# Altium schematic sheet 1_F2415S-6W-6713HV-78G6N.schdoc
size 289 x 200 mm; Name: default297x210; Symbol: default297x210; Device: default297x210; Date: 2025.06.26; Rev: V1.1; Size: "A4"; Id: /; File: F2415S-6W-6713HV-78G6N; Sheet: /; @Page No: 1; @Page Count: 1; @Schematic Name: F2415S-6W-6713HV-78G6N; @Project Name: 全桥隔离电源-B2415D-6W-6713HV-78G6N; @Board Name: B2415D-6W-6713HV-78G6N; @Update Date: 2025-06-26; @Create Time: 15:58:33; @Update Time: 15:58:34; @Page Name: F2415S-6W-6713HV-78G6N; @Create Date: 2025-06-26
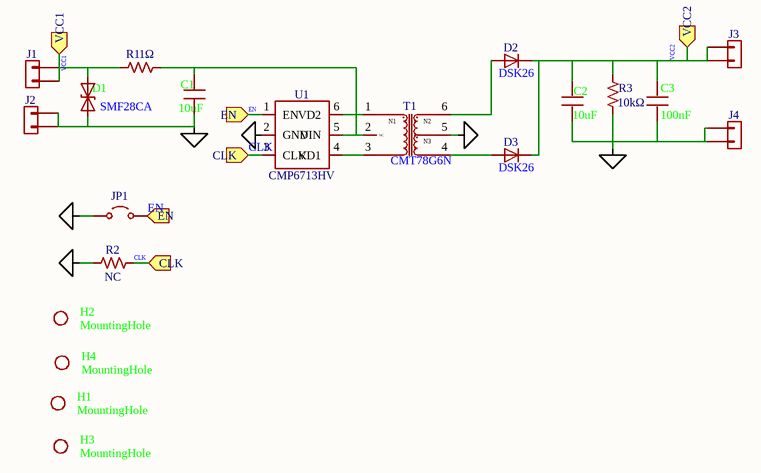
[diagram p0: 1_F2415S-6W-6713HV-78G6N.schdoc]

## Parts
C1  10uF  [C0805]
C2  10uF  [C0805]
C3  100nF  [C0603]
D1  SMF28CA  [SOD-123FL_L2.8-W1.8-LS3.7-BI]
D2  DSK26  [SOD-123_L2.8-W1.8-LS3.7-RD]
D3  DSK26  [SOD-123_L2.8-W1.8-LS3.7-RD]
H1  value MountingHole  [MountingHole:MountingHole_3.2mm_M3]  (hidden comment: Mechanical_MountingHole)
H2  value MountingHole  [MountingHole:MountingHole_3.2mm_M3]  (hidden comment: Mechanical_MountingHole)
H3  value MountingHole  [MountingHole:MountingHole_3.2mm_M3]  (hidden comment: Mechanical_MountingHole)
H4  value MountingHole  [MountingHole:MountingHole_3.2mm_M3]  (hidden comment: Mechanical_MountingHole)
J1  Connector_Generic_Conn_01x02  [Connector_PinHeader_2.54mm:PinHeader_1x02_P2.54mm_Vertical]  (value not drawn)
J2  Connector_Generic_Conn_01x02  [Connector_PinHeader_2.54mm:PinHeader_1x02_P2.54mm_Vertical]  (value not drawn)
J3  Connector_Generic_Conn_01x02  [Connector_PinHeader_2.54mm:PinHeader_1x02_P2.54mm_Vertical]  (value not drawn)
J4  Connector_Generic_Conn_01x02  [Connector_PinHeader_2.54mm:PinHeader_1x02_P2.54mm_Vertical]  (value not drawn)
JP1  Jumper_Jumper_2_Open  [Connector_PinHeader_2.54mm:PinHeader_1x02_P2.54mm_Vertical]  (value not drawn)
R1  1Ω  [R0603]
R2  NC  [R0603]
R3  10kΩ  [R0603]
T1  CMT78G6N  [XFMR-SMD_6P-L9.3-W8.8-P2.54-LS12.6]
U1  CMP6713HV  [Package_TO_SOT_SMD:TSOT-23-6]

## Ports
CLK (in), EN (in), VCC1 (in), VCC2 (in)

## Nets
GND1: C1.1 D1.2 J2.1 J2.2 JP1.1 R2.1 U1.2(GND)
GND2: C2.1 C3.1 J4.1 J4.2 R3.2 T1.5
CLK: R2.2 U1.3(CLK) ; port CLK
EN: JP1.2 U1.1(EN) ; port EN
VCC1: D1.1 J1.1 J1.2 R1.1 ; port VCC1
VCC2: C2.2 C3.2 D2.1 D3.1 J3.1 J3.2 R3.1 ; port VCC2
NetC1_2: C1.2 R1.2 T1.2 U1.5(VIN)
NetD2_2: D2.2 T1.6
NetD3_2: D3.2 T1.4
NetT1_1: T1.1 U1.6(VD2)
NetT1_3: T1.3 U1.4(VD1)

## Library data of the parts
C1 = CGA0805X5R106K350MT: Manufacturer: HRE(芯声); Symbol: My_Library_C; Add into BOM: yes; Tolerance: ±10%; Voltage Rating: 35V; Temperature Coefficient: X5R
C2 = CC0805KKX5R8BB106_C89831: Manufacturer: YAGEO(国巨); Symbol: My_Library_C; Add into BOM: yes; Tolerance: ±10%; Voltage Rated: 25V; Temperature Coefficient: X5R
C3 = CC0603KRX7R9BB104: Manufacturer: YAGEO(国巨); Symbol: My_Library_C; Add into BOM: yes; Tolerance: ±10%; Voltage Rating: 50V; Temperature Coefficient: X7R
D1 = SMF28CA_C364280: Manufacturer: MDD(辰达半导体); Symbol: Diode_SMAJ30CA; Add into BOM: yes; polarity: 双向; Reverse Stand-Off Voltage (Vrwm): 28V; Maximum Clamping Voltage: 45.4V; Peak Pulse Current (Ipp): 4.4A; Peak Pulse Power Dissipation (Ppp): 200W; Breakdown Voltage: 34.4V; Reverse Leakage Current (Ir): 1uA; Type: TVS
D2 D3 = DSK26_C50553: Manufacturer: MDD(辰达半导体); Symbol: My_Library_D; Add into BOM: yes; Diode Configuration: 独立式; Forward Voltage (Vf@If): 700mV@2A; Reverse Voltage (Vr): 60V; Rectified Current: 2A; Reverse Leakage Current (Ir): 500uA@60V
H1-H4 = Mechanical_MountingHole: Users: REF**; ki_fp_filters: MountingHole*; Add into BOM: yes
J1-J4 = Connector_Generic_Conn_01x02: Users: REF**; ki_fp_filters: Jumper* TestPoint*2Pads* TestPoint*Bridge*; Add into BOM: yes
JP1 = Jumper_Jumper_2_Open: Add into BOM: yes
R1 = RC0603FR-071RL: Manufacturer: YAGEO(国巨); Symbol: My_Library_R; Add into BOM: yes; Tolerance: ±1%; Power(Watts): 100mW; Overload Voltage (Max): 75V; Temperature Coefficient: ±200ppm/℃
R2 = RC0603FR-0715KL: Symbol: My_Library_R; Add into BOM: yes; Tolerance: ±1%
R3 = RC0603FR-0710KL: Manufacturer: YAGEO(国巨); Symbol: My_Library_R; Add into BOM: yes; Tolerance: ±1%; Power(Watts): 100mW; Overload Voltage (Max): 75V; Temperature Coefficient: ±100ppm/℃
T1 = CMT78G6N: Manufacturer: coileasy(线易); Symbol: My_Library_VPT85BB-02A; Add into BOM: yes
U1 = CMP6713HV: Manufacturer: coileasy(线易); Symbol: MYLibrary_CMP6713RE/HV; Add into BOM: yes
